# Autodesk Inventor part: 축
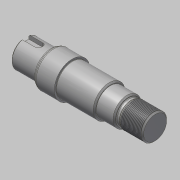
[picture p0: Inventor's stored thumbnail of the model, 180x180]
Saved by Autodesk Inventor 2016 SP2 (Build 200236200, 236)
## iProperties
Created: 2019-05
Part Number: 축
Material: 강철, 연강
Document SubType Name: Modeling
Designer: mduedu
Density: 1 g/cm^3
Appearance: 강철
Author: mduedu
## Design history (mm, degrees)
sketch "스케치1"
  geometry: L1 (0, 0)-(20, 0); L2 (20, 0)-(20, 11); L3 (20, 11)-(0, 11); L4 (0, 11)-(0, 0); L5 (20, 0)-(37, 0); L6 (37, 0)-(37, 14); L7 (37, 14)-(20, 14); L8 (20, 14)-(20, 0); L9 (37, 0)-(67, 0); L10 (67, 0)-(67, 12.5); L11 (67, 12.5)-(37, 12.5); L12 (37, 12.5)-(37, 0); L13 (67, 0)-(81, 0); L14 (81, 0)-(81, 11); L15 (81, 11)-(67, 11); L16 (67, 11)-(67, 0); L17 (81, 0)-(102, 0); L18 (102, 0)-(102, 10); L19 (102, 10)-(81, 10); L20 (81, 10)-(81, 0)
  constraints: 40 end point, 10 parallel, 5 horizontal, 5 perpendicular
  dimensions: "d0" = 102 distance between parallel lines of L18 L4; "d2" = 21 distance of L18.end L19.end; "d3" = 14 distance of L14.end L15.end; "d4" = 30 distance of L10.end L11.end; "d5" = 17 distance of L6.end L7.end; "d6" = 22 diameter of L3 L1; "d7" = 28 diameter of L7 L5; "d8" = 25 diameter of L11 L9; "d9" = 22 diameter of L15 L13; "d10" = 20 diameter of L19 L17
revolve "회전1" sketch "스케치1" stored, may be unused: angle "d11" = 90 deg
chamfer "모따기1" distance "d12" = 2.34; stored, may be unused: second distance "d13" = 2, angle "d14" = 30 deg
fillet "모깎기1" dims "d15" = 2, "d16" = 1
fillet "모깎기2" dims "d17" = 0.3
chamfer "모따기2" distance "d18" = 1; stored, may be unused: second distance "d19" = 2, angle "d20" = 30 deg
sketch "스케치2"
  geometry: L1 (102, -10)-(81, -10) reference; L2 (81, -10)-(81, -11) reference; L3 (81, -11)-(67, -11) reference; L4 (67, -11)-(67, -11.5) reference; L5 (67, -11.5)-(66, -12.5) reference; L6 (66, -12.5)-(37.3, -12.5) reference; L7 (37, -12.8)-(37, -14) reference; L8 (37, -14)-(22.876, -14) reference; L9 (21.876, -13.732)-(20.5, -12.938) reference; L10 (20, -12.072)-(20, -11) reference; L11 (20, -11)-(0, -11) reference; L12 (0, -11)-(0, 11) reference; L13 (0, 11)-(20, 11) reference; L14 (20, 11)-(20, 12.072) reference; L15 (20.5, 12.938)-(21.876, 13.732) reference; L16 (22.876, 14)-(37, 14) reference; L17 (37, 14)-(37, 12.8) reference; L18 (37.3, 12.5)-(66, 12.5) reference; L19 (66, 12.5)-(67, 11.5) reference; L20 (67, 11.5)-(67, 11) reference; L21 (67, 11)-(81, 11) reference; L22 (81, 11)-(81, 10) reference; L23 (81, 10)-(102, 10) reference; L24 (102, 10)-(102, -10) reference; L25 (0, 0)-(102, 0); L26 (81, 10)-(84.726, 10); L27 (83.34, 9.2)-(81, 9.2); L28 (81, 9.2)-(81, 10); L29 (84.726, 10)-(83.34, 9.2); A1 r 0.3 centre (37.3, -12.8) between (37.3, -12.5) and (37, -12.8) reference; A2 r 2 centre (22.876, -12) between (21.876, -13.732) and (22.876, -14) reference; A3 r 1 centre (21, -12.072) between (20, -12.072) and (20.5, -12.938) reference; A4 r 1 centre (21, 12.072) between (20.5, 12.938) and (20, 12.072) reference; A5 r 2 centre (22.876, 12) between (22.876, 14) and (21.876, 13.732) reference; A6 r 0.3 centre (37.3, 12.8) between (37, 12.8) and (37.3, 12.5) reference
  constraints: 10 end point, 1 horizontal, 1 midpoint, 1 parallel, 1 vertical
  dimensions: "d21" = 18.4 diameter of L27 L25; "d23" = 2.34 distance of L27.start L27.end; "d24" = 30 deg angle of L23 L29
revolve "회전2" sketch "스케치2" stored, may be unused: angle "d25" = 90 deg
fillet "모깎기3" dims "d26" = 0.6
chamfer "모따기3" distance "d27" = 1; stored, may be unused: second distance "d28" = 2, angle "d29" = 30 deg
feature "스레드1" dims "d30" = 10, "d31" = 0
chamfer "모따기4" distance "d32" = 1; stored, may be unused: second distance "d33" = 2, angle "d34" = 30 deg
node "작업 평면1"
sketch "스케치3"
  geometry: L1 (10, -3)-(-1, -3); L2 (-1, -3)-(-1, 3); L3 (-1, 3)-(10, 3); L4 (10, 3)-(10, -3); 3 further points
  constraints: 8 end point, 2 midpoint, 2 parallel, 1 coincident, 1 horizontal, 1 perpendicular, 1 vertical alignment, 2 other
  dimensions: "d35" = 14 dimension on L4; "d37" = 6 distance between parallel lines of L3 L1
extrude "돌출1" cut sketch "스케치3" distance "d38" = 3.5; taper "d39" = 0 deg
chamfer "모따기5" distance "d40" = 1; stored, may be unused: second distance "d41" = 2, angle "d42" = 30 deg
node "솔리드1"
node "절단 모서리 투영1"
